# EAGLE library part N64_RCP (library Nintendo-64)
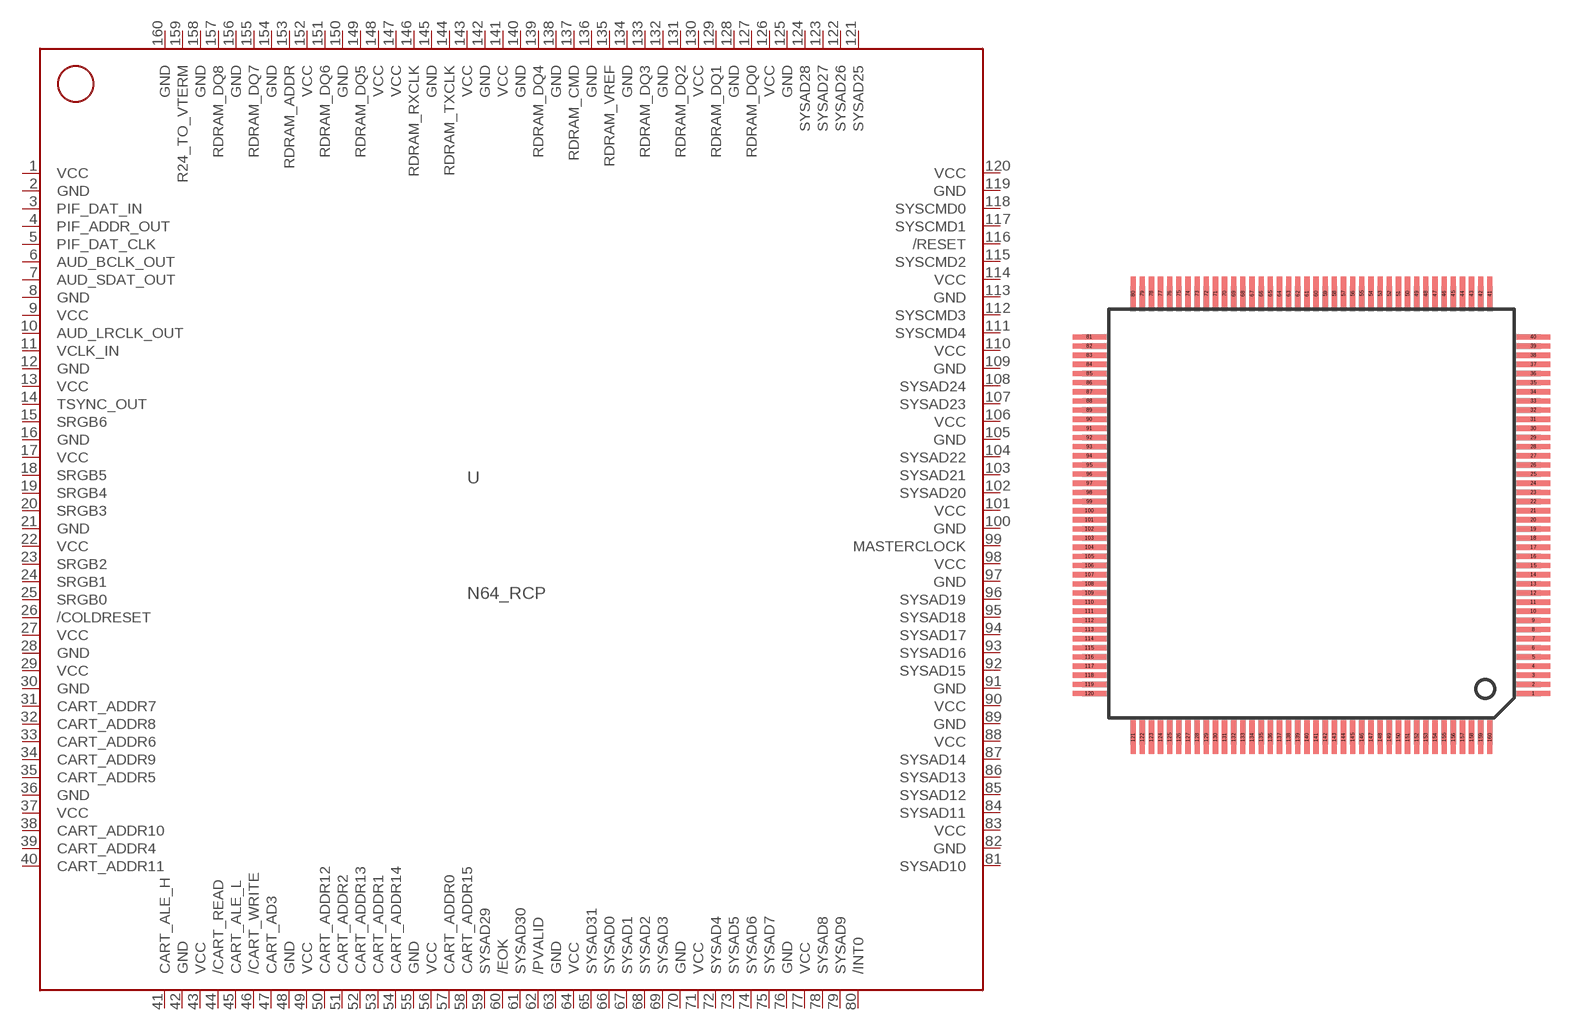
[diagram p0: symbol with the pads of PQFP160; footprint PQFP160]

Designator prefix -

## N64_RCP  [PQFP160]
1  VCC  pwr
2  GND  pwr
3  PIF_DAT_IN
4  PIF_ADDR_OUT
5  PIF_DAT_CLK
6  AUD_BCLK_OUT  out
7  AUD_SDAT_OUT  out
8  GND  pwr
9  VCC  pwr
10  AUD_LRCLK_OUT  out
11  VCLK_IN
12  GND  pwr
13  VCC  pwr
14  TSYNC_OUT  out
15  SRGB6  out
16  GND  pwr
17  VCC  pwr
18  SRGB5  out
19  SRGB4  out
20  SRGB3  out
21  GND  pwr
22  VCC  pwr
23  SRGB2  out
24  SRGB1  out
25  SRGB0  out
26  /COLDRESET
27  VCC  pwr
28  GND  pwr
29  VCC  pwr
30  GND  pwr
31  CART_ADDR7
32  CART_ADDR8
33  CART_ADDR6
34  CART_ADDR9
35  CART_ADDR5
36  GND  pwr
37  VCC  pwr
38  CART_ADDR10
39  CART_ADDR4
40  CART_ADDR11
41  CART_ALE_H  out
42  GND  pwr
43  VCC  pwr
44  /CART_READ  out
45  CART_ALE_L  out
46  /CART_WRITE  out
47  CART_AD3
48  GND  pwr
49  VCC  pwr
50  CART_ADDR12
51  CART_ADDR2
52  CART_ADDR13
53  CART_ADDR1
54  CART_ADDR14
55  GND  pwr
56  VCC  pwr
57  CART_ADDR0
58  CART_ADDR15
59  SYSAD29
60  /EOK  out
61  SYSAD30
62  /PVALID  in
63  GND  pwr
64  VCC  pwr
65  SYSAD31
66  SYSAD0
67  SYSAD1
68  SYSAD2
69  SYSAD3
70  GND  pwr
71  VCC  pwr
72  SYSAD4
73  SYSAD5
74  SYSAD6
75  SYSAD7
76  GND  pwr
77  VCC  pwr
78  SYSAD8
79  SYSAD9
80  /INT0  out
81  SYSAD10
82  GND  pwr
83  VCC  pwr
84  SYSAD11
85  SYSAD12
86  SYSAD13
87  SYSAD14
88  VCC  pwr
89  GND  pwr
90  VCC  pwr
91  GND  pwr
92  SYSAD15
93  SYSAD16
94  SYSAD17
95  SYSAD18
96  SYSAD19
97  GND  pwr
98  VCC  pwr
99  MASTERCLOCK  out
100  GND  pwr
101  VCC  pwr
102  SYSAD20
103  SYSAD21
104  SYSAD22
105  GND  pwr
106  VCC  pwr
107  SYSAD23
108  SYSAD24
109  GND  pwr
110  VCC  pwr
111  SYSCMD4
112  SYSCMD3
113  GND  pwr
114  VCC  pwr
115  SYSCMD2
116  /RESET  out
117  SYSCMD1
118  SYSCMD0
119  GND  pwr
120  VCC  pwr
121  SYSAD25
122  SYSAD26
123  SYSAD27
124  SYSAD28
125  GND  pwr
126  VCC  pwr
127  RDRAM_DQ0
128  GND  pwr
129  RDRAM_DQ1
130  VCC  pwr
131  RDRAM_DQ2
132  GND  pwr
133  RDRAM_DQ3
134  GND  pwr
135  RDRAM_VREF
136  GND  pwr
137  RDRAM_CMD
138  GND  pwr
139  RDRAM_DQ4
140  GND  pwr
141  VCC  pwr
142  GND  pwr
143  VCC  pwr
144  RDRAM_TXCLK
145  GND  pwr
146  RDRAM_RXCLK
147  VCC  pwr
148  VCC  pwr
149  RDRAM_DQ5
150  GND  pwr
151  RDRAM_DQ6
152  VCC  pwr
153  RDRAM_ADDR
154  GND  pwr
155  RDRAM_DQ7
156  GND  pwr
157  RDRAM_DQ8
158  GND  pwr
159  R24_TO_VTERM  in
160  GND  pwr

## Footprint PQFP160 (pad centres in mm)
smd 2.4 x 0.37: 1 15.775,-12.675; 2 15.775,-12.025; 3 15.775,-11.375; 4 15.775,-10.725; 5 15.775,-10.075; 6 15.775,-9.425; 7 15.775,-8.775; 8 15.775,-8.125; 9 15.775,-7.475; 10 15.775,-6.825; 11 15.775,-6.175; 12 15.775,-5.525; 13 15.775,-4.875; 14 15.775,-4.225; 15 15.775,-3.575; 16 15.775,-2.925; 17 15.775,-2.275; 18 15.775,-1.625; 19 15.775,-0.975; 20 15.775,-0.325; 21 15.775,0.325; 22 15.775,0.975; 23 15.775,1.625; 24 15.775,2.275; 25 15.775,2.925; 26 15.775,3.575; 27 15.775,4.225; 28 15.775,4.875; 29 15.775,5.525; 30 15.775,6.175; 31 15.775,6.825; 32 15.775,7.475; 33 15.775,8.125; 34 15.775,8.775; 35 15.775,9.425; 36 15.775,10.075; 37 15.775,10.725; 38 15.775,11.375; 39 15.775,12.025; 40 15.775,12.675; 81 -15.775,12.675; 82 -15.775,12.025; 83 -15.775,11.375; 84 -15.775,10.725; 85 -15.775,10.075; 86 -15.775,9.425; 87 -15.775,8.775; 88 -15.775,8.125; 89 -15.775,7.475; 90 -15.775,6.825; 91 -15.775,6.175; 92 -15.775,5.525; 93 -15.775,4.875; 94 -15.775,4.225; 95 -15.775,3.575; 96 -15.775,2.925; 97 -15.775,2.275; 98 -15.775,1.625; 99 -15.775,0.975; 100 -15.775,0.325; 101 -15.775,-0.325; 102 -15.775,-0.975; 103 -15.775,-1.625; 104 -15.775,-2.275; 105 -15.775,-2.925; 106 -15.775,-3.575; 107 -15.775,-4.225; 108 -15.775,-4.875; 109 -15.775,-5.525; 110 -15.775,-6.175; 111 -15.775,-6.825; 112 -15.775,-7.475; 113 -15.775,-8.125; 114 -15.775,-8.775; 115 -15.775,-9.425; 116 -15.775,-10.075; 117 -15.775,-10.725; 118 -15.775,-11.375; 119 -15.775,-12.025; 120 -15.775,-12.675
smd 0.37 x 2.4: 41 12.675,15.775; 42 12.025,15.775; 43 11.375,15.775; 44 10.725,15.775; 45 10.075,15.775; 46 9.425,15.775; 47 8.775,15.775; 48 8.125,15.775; 49 7.475,15.775; 50 6.825,15.775; 51 6.175,15.775; 52 5.525,15.775; 53 4.875,15.775; 54 4.225,15.775; 55 3.575,15.775; 56 2.925,15.775; 57 2.275,15.775; 58 1.625,15.775; 59 0.975,15.775; 60 0.325,15.775; 61 -0.325,15.775; 62 -0.975,15.775; 63 -1.625,15.775; 64 -2.275,15.775; 65 -2.925,15.775; 66 -3.575,15.775; 67 -4.225,15.775; 68 -4.875,15.775; 69 -5.525,15.775; 70 -6.175,15.775; 71 -6.825,15.775; 72 -7.475,15.775; 73 -8.125,15.775; 74 -8.775,15.775; 75 -9.425,15.775; 76 -10.075,15.775; 77 -10.725,15.775; 78 -11.375,15.775; 79 -12.025,15.775; 80 -12.675,15.775; 121 -12.675,-15.775; 122 -12.025,-15.775; 123 -11.375,-15.775; 124 -10.725,-15.775; 125 -10.075,-15.775; 126 -9.425,-15.775; 127 -8.775,-15.775; 128 -8.125,-15.775; 129 -7.475,-15.775; 130 -6.825,-15.775; 131 -6.175,-15.775; 132 -5.525,-15.775; 133 -4.875,-15.775; 134 -4.225,-15.775; 135 -3.575,-15.775; 136 -2.925,-15.775; 137 -2.275,-15.775; 138 -1.625,-15.775; 139 -0.975,-15.775; 140 -0.325,-15.775; 141 0.325,-15.775; 142 0.975,-15.775; 143 1.625,-15.775; 144 2.275,-15.775; 145 2.925,-15.775; 146 3.575,-15.775; 147 4.225,-15.775; 148 4.875,-15.775; 149 5.525,-15.775; 150 6.175,-15.775; 151 6.825,-15.775; 152 7.475,-15.775; 153 8.125,-15.775; 154 8.775,-15.775; 155 9.425,-15.775; 156 10.075,-15.775; 157 10.725,-15.775; 158 11.375,-15.775; 159 12.025,-15.775; 160 12.675,-15.775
